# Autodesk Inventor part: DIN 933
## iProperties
Author: Cor de Vlaming
Shininess: 64.0
Angle Display Precision: 2
Document Length Units: 11269
Document Angle Units: 11283
Document Time Units: 11279
Document Mass Units: 11290
Document Length Units Precision: 3
Document Angle Units Precision: 2
Compacted: True
PropertySet Name: _Private Model Information
Created: 2002-08
Part Number: DIN 933
Material: Boutklasse 8.8
Description: Zeskantbout
Document SubType Name: Modeling
Designer: Cor de Vlaming
Engineer: Cor de Vlaming
Control State: 0
Master: False
Checked Out: False
PropertySet Name: Design Tracking Control
Density: 0.0
Volumn: 0.0
Area: 0.0
PropertySet Name: Model Information
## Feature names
1. Extrusion1
2. Extrusion3
3. Chamfer1
4. Revolution1
5. Extrusion4
6. Chamfer3
